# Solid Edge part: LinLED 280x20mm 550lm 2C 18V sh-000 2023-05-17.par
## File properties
Author: jaroslaw.przewlocki
Template: iso metric part.par
Last saved by: jaroslaw.przewlocki
Revision: 1
Application: Solid Edge
Gęstość: 0,000 kg/m^3
Dokładność: 0,990
Username: jaroslaw.przewlocki
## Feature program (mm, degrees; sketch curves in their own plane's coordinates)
body "unnamed Body 1"
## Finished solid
Body 1: solid body, 814 faces, 2098 edges, 1340 vertices.
  Faces by surface: plane 509, cylinder 149, torus 64, cone 50, spline 26, sphere 16
  Edges by curve: line 1452, curve on surface 356, circle 188, ellipse 66, spline 36
Bounding box of the edges (mm; curved faces can reach further): 279.600 x 20.000 x 4.450, from (-139.8, -10, -1) to (139.8, 10, 3.45).
Cylindrical faces by radius (mm): R0.2 x46, R0.2169 x6, R0.25 x22, R0.3373 x6, R0.4 x8, R0.4006 x2, R0.4008 x2, R0.525 x2, R0.6 x20, R1 x12, R1.1 x4, R1.1989 x2, R1.199 x2, R1.2 x10, R2.15 x5
Conical faces (half-angle, radius in mm at the cone's reference point): 0.398 deg R1.1964 x2, 0.4493 deg R1.1964 x2, 0.4746 deg R1.1948 x2, 0.4758 deg R1.1948 x2, 0.5 deg R0.5056 x4, 0.5 deg R1.0082 x4, 1 deg R0.5511 x2, 10 deg R0.2132 x4, 10 deg R0.4132 x4, 16.0099 deg R1.1053 x2, 16.1249 deg R1.1279 x2, 18.8604 deg R1.0669 x4, 19.5041 deg R0.5138 x2, 19.8244 deg R0.5099 x2, 27.363 deg R0.6214 x2, 40.6434 deg R0.5161 x2, 43.3309 deg R0.4892 x2, 45 deg R0.575 x2, 45 deg R0.625 x4
Toroidal faces (ring radius, tube radius in mm): R0.0958 r0.3997 x4, R0.1076 r0.4 x2, R0.1101 r0.4001 x2, R0.1217 r0.4 x2, R0.1234 r0.4 x2, R0.1626 r0.228 x2, R0.1634 r0.2287 x2, R0.3287 r0.2001 x2, R0.3684 r0.2151 x2, R0.3703 r0.4 x2, R0.3818 r0.2 x4, R0.4166 r0.3983 x2, R0.5981 r0.197 x2, R0.5982 r0.197 x2, R0.6009 r0.3968 x2, R0.6009 r0.3969 x2, R0.6227 r0.2 x2, R0.6235 r0.2 x2, R0.8 r0.2 x4, R0.8522 r0.3 x2, R0.9002 r0.2 x2, R0.9018 r0.2 x2, R0.9197 r0.223 x2, R0.9365 r0.2 x2, R0.9663 r0.2263 x2, R0.9665 r0.2263 x2, R1.429 r1.2 x2, R1.8741 r0.2175 x2, R1.9007 r0.2 x2
Spherical faces by radius (mm): R0.2 x12, R0.6 x4
Planar faces by outward normal: +x 57, +y 60, +z 79, -x 57, -y 61, -z 9, oblique 186
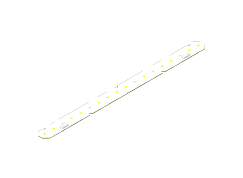
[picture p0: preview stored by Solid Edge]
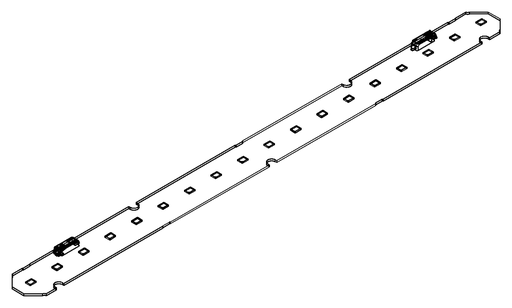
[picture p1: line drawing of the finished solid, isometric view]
